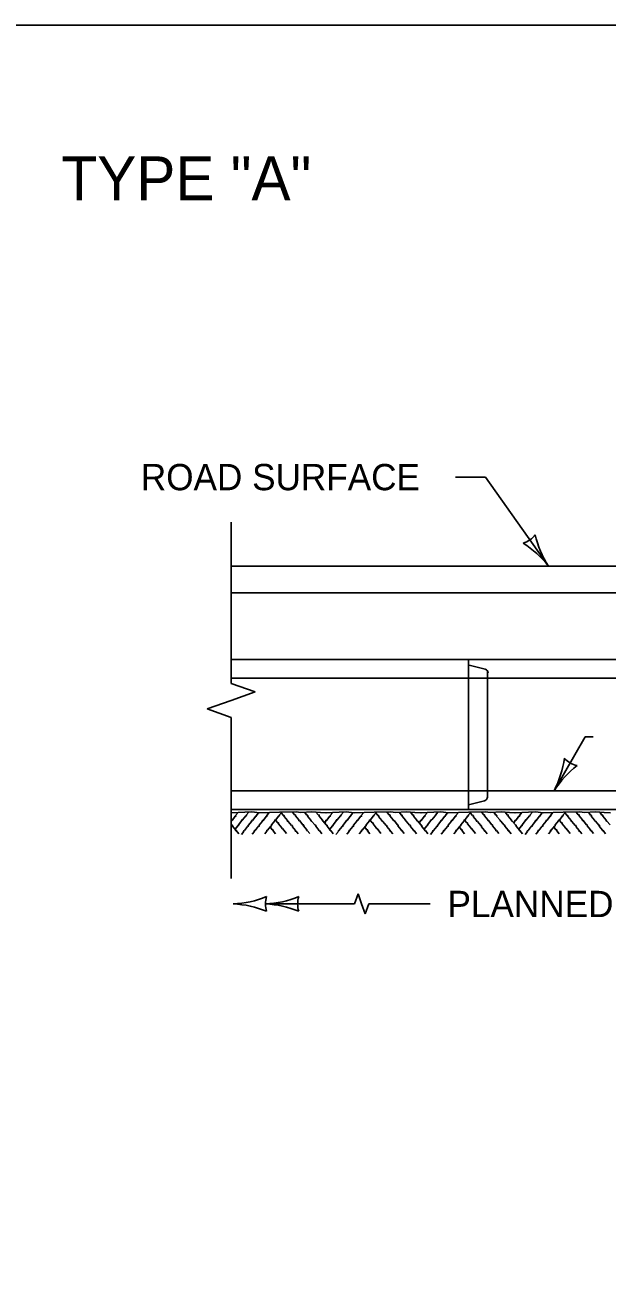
# Model space of a CAD drawing. Extents: x 49991.4 to 50021, y 49987.6 to 50011.4.
# Drawn here: x 50003.231 to 50004.56, y 49996.145 to 49998.999 of the extents above; entities that cross this region are included whole.
import ezdxf

# ---------------------------------------------------------------- set-up
doc = ezdxf.new("R2010")
doc.units = 0
for name, color, linetype in [('Level 1', 7, 'Continuous'), ('Level 2', 7, 'Continuous'), ('Level 3', 7, 'Continuous'), ('Level 4', 7, 'Continuous'), ('Level 6', 7, 'Continuous')]:
    doc.layers.add(name, color=color, linetype=linetype)

msp = doc.modelspace()

# ---------------------------------------------------------------- linework, layer by layer
at = {"layer": 'Level 1'}
for p, q in [((50003.7019, 49997.7029), (50003.702, 49997.7636)), ((50003.702, 49997.7636), (50004.9281, 49997.7636)), ((50005.2161, 49997.7029), (50003.7019, 49997.7029)), ((50003.7036, 49997.7029), (50003.7047, 49997.7029)), ((50003.702, 49997.5504), (50005.9421, 49997.5504)), ((50004.2441, 49997.5504), (50004.2441, 49997.208)), ((50006.3273, 49997.208), (50003.702, 49997.208))]:
    msp.add_line(p, q, dxfattribs=at)
msp.add_lwpolyline([(49999.3835, 49998.9992), (50016.7501, 49998.9992), (50016.7501, 49987.7988), (49999.3835, 49987.7988)], close=True, dxfattribs=at)
for points in [[(50003.7015, 49997.2006), (50003.7485, 49997.2025), (50003.7665, 49997.2004), (50003.8121, 49997.2019), (50003.8505, 49997.2022), (50003.8609, 49997.2007), (50003.8861, 49997.2025), (50003.9055, 49997.2013), (50003.9201, 49997.2006)], [(50003.7179, 49997.2012), (50003.7119, 49997.1941), (50003.7125, 49997.1926), (50003.7109, 49997.1926), (50003.7037, 49997.183), (50003.7029, 49997.183)], [(50003.742, 49997.202), (50003.736, 49997.195), (50003.7367, 49997.1936), (50003.7353, 49997.1936), (50003.7279, 49997.184), (50003.7258, 49997.184), (50003.7263, 49997.1824), (50003.7185, 49997.1726), (50003.7185, 49997.171), (50003.7168, 49997.1704), (50003.7108, 49997.1626)], [(50003.7639, 49997.2004), (50003.7585, 49997.1936), (50003.7589, 49997.1923), (50003.7577, 49997.1923), (50003.7503, 49997.1827), (50003.7483, 49997.1827), (50003.7485, 49997.181), (50003.7408, 49997.1713), (50003.7408, 49997.1696), (50003.7391, 49997.1689), (50003.7319, 49997.1596), (50003.7301, 49997.1593), (50003.7305, 49997.1576), (50003.7253, 49997.151)], [(50003.7888, 49997.2012), (50003.7828, 49997.1941), (50003.7835, 49997.1926), (50003.7821, 49997.1926), (50003.7749, 49997.183), (50003.7727, 49997.183), (50003.7729, 49997.1812), (50003.7654, 49997.1718), (50003.7654, 49997.1698), (50003.7635, 49997.1692), (50003.7564, 49997.1598), (50003.7545, 49997.1598), (50003.7549, 49997.1578), (50003.7497, 49997.1515)], [(50003.8173, 49997.202), (50003.8115, 49997.1947), (50003.8121, 49997.1935), (50003.8109, 49997.1935), (50003.8033, 49997.1839), (50003.8014, 49997.1839), (50003.8015, 49997.1822), (50003.7939, 49997.1726), (50003.7939, 49997.1707), (50003.7923, 49997.1702), (50003.7849, 49997.1608), (50003.7833, 49997.1606), (50003.7835, 49997.1587), (50003.7783, 49997.1524)], [(50003.8547, 49997.1524), (50003.8499, 49997.1587), (50003.8483, 49997.1584), (50003.8487, 49997.1598), (50003.841, 49997.169), (50003.8415, 49997.171), (50003.8397, 49997.1712), (50003.832, 49997.1808), (50003.8303, 49997.1812), (50003.8301, 49997.183), (50003.8225, 49997.1922), (50003.8229, 49997.1941), (50003.8211, 49997.1941), (50003.8158, 49997.2006)], [(50003.8811, 49997.153), (50003.8755, 49997.1602), (50003.874, 49997.1599), (50003.8743, 49997.1612), (50003.8667, 49997.1706), (50003.8673, 49997.1725), (50003.8653, 49997.1726), (50003.8577, 49997.1824), (50003.856, 49997.1827), (50003.8559, 49997.1845), (50003.8483, 49997.1936), (50003.8485, 49997.1956), (50003.8465, 49997.1956), (50003.8415, 49997.202)], [(50003.9089, 49997.1522), (50003.9034, 49997.1596), (50003.9019, 49997.1592), (50003.9021, 49997.1605), (50003.8949, 49997.1701), (50003.8951, 49997.1718), (50003.8933, 49997.172), (50003.8855, 49997.1816), (50003.8839, 49997.1821), (50003.8837, 49997.1838), (50003.8763, 49997.193), (50003.8764, 49997.1947), (50003.8745, 49997.1947), (50003.8695, 49997.2016)], [(50003.919, 49997.1726), (50003.9118, 49997.1816), (50003.9101, 49997.1822), (50003.91, 49997.1839), (50003.9023, 49997.193), (50003.9027, 49997.195), (50003.9009, 49997.195), (50003.8953, 49997.2019)], [(50003.9175, 49997.2006), (50003.9645, 49997.2025), (50003.9823, 49997.2004), (50004.0281, 49997.2019), (50004.0665, 49997.2022), (50004.0773, 49997.2007), (50004.1021, 49997.2025), (50004.1213, 49997.2013), (50004.1361, 49997.2006)], [(50003.9339, 49997.2012), (50003.9279, 49997.1941), (50003.9285, 49997.1926), (50003.9269, 49997.1926), (50003.9197, 49997.183), (50003.9189, 49997.183)], [(50003.958, 49997.202), (50003.952, 49997.195), (50003.9527, 49997.1936), (50003.9513, 49997.1936), (50003.9439, 49997.184), (50003.9418, 49997.184), (50003.9423, 49997.1824), (50003.9345, 49997.1726), (50003.9345, 49997.171), (50003.9328, 49997.1704), (50003.9267, 49997.1626)], [(50003.9799, 49997.2004), (50003.9743, 49997.1936), (50003.9749, 49997.1923), (50003.9735, 49997.1923), (50003.9663, 49997.1827), (50003.9643, 49997.1827), (50003.9645, 49997.181), (50003.9568, 49997.1713), (50003.9568, 49997.1696), (50003.9551, 49997.1689), (50003.9478, 49997.1596), (50003.9461, 49997.1593), (50003.9465, 49997.1576), (50003.9411, 49997.151)], [(50004.0048, 49997.2012), (50003.9987, 49997.1941), (50003.9994, 49997.1926), (50003.9981, 49997.1926), (50003.9905, 49997.183), (50003.9887, 49997.183), (50003.9889, 49997.1812), (50003.9813, 49997.1718), (50003.9813, 49997.1698), (50003.9795, 49997.1692), (50003.9723, 49997.1598), (50003.9705, 49997.1598), (50003.9709, 49997.1578), (50003.9657, 49997.1515)], [(50004.0333, 49997.202), (50004.0273, 49997.1947), (50004.0281, 49997.1935), (50004.0265, 49997.1935), (50004.0193, 49997.1839), (50004.0174, 49997.1839), (50004.0175, 49997.1822), (50004.0099, 49997.1726), (50004.0099, 49997.1707), (50004.0083, 49997.1702), (50004.0009, 49997.1608), (50003.9993, 49997.1606), (50003.9995, 49997.1587), (50003.9941, 49997.1524)], [(50004.0707, 49997.1524), (50004.0659, 49997.1587), (50004.0643, 49997.1584), (50004.0645, 49997.1598), (50004.057, 49997.169), (50004.0573, 49997.171), (50004.0557, 49997.1712), (50004.048, 49997.1808), (50004.0463, 49997.1812), (50004.0461, 49997.183), (50004.0385, 49997.1922), (50004.0389, 49997.1941), (50004.0369, 49997.1941), (50004.0318, 49997.2006)], [(50004.0971, 49997.153), (50004.0915, 49997.1602), (50004.09, 49997.1599), (50004.0901, 49997.1612), (50004.0827, 49997.1706), (50004.0829, 49997.1725), (50004.0813, 49997.1726), (50004.0737, 49997.1824), (50004.072, 49997.1827), (50004.0719, 49997.1845), (50004.0643, 49997.1936), (50004.0645, 49997.1956), (50004.0625, 49997.1956), (50004.0575, 49997.202)], [(50004.1249, 49997.1522), (50004.1194, 49997.1596), (50004.1179, 49997.1592), (50004.1181, 49997.1605), (50004.1105, 49997.1701), (50004.111, 49997.1718), (50004.1093, 49997.172), (50004.1015, 49997.1816), (50004.0999, 49997.1821), (50004.0997, 49997.1838), (50004.0923, 49997.193), (50004.0924, 49997.1947), (50004.0905, 49997.1947), (50004.0855, 49997.2016)], [(50004.135, 49997.1726), (50004.1278, 49997.1816), (50004.126, 49997.1822), (50004.1259, 49997.1839), (50004.1183, 49997.193), (50004.1185, 49997.195), (50004.1165, 49997.195), (50004.1113, 49997.2019)], [(50004.1335, 49997.2006), (50004.1805, 49997.2025), (50004.1983, 49997.2004), (50004.2441, 49997.2019), (50004.2825, 49997.2022), (50004.2929, 49997.2007), (50004.318, 49997.2025), (50004.3373, 49997.2013), (50004.3521, 49997.2006)], [(50004.1499, 49997.2012), (50004.1439, 49997.1941), (50004.1445, 49997.1926), (50004.1429, 49997.1926), (50004.1357, 49997.183), (50004.1349, 49997.183)], [(50004.1739, 49997.202), (50004.168, 49997.195), (50004.1685, 49997.1936), (50004.1673, 49997.1936), (50004.1597, 49997.184), (50004.1578, 49997.184), (50004.1579, 49997.1824), (50004.1503, 49997.1726), (50004.1503, 49997.171), (50004.1487, 49997.1704), (50004.1427, 49997.1626)], [(50004.1959, 49997.2004), (50004.1905, 49997.1936), (50004.1909, 49997.1923), (50004.1897, 49997.1923), (50004.1823, 49997.1827), (50004.1803, 49997.1827), (50004.1805, 49997.181), (50004.1728, 49997.1713), (50004.1728, 49997.1696), (50004.1711, 49997.1689), (50004.1638, 49997.1596), (50004.162, 49997.1593), (50004.1623, 49997.1576), (50004.1571, 49997.151)], [(50004.2208, 49997.2012), (50004.2147, 49997.1941), (50004.2154, 49997.1926), (50004.2141, 49997.1926), (50004.2065, 49997.183), (50004.2047, 49997.183), (50004.2049, 49997.1812), (50004.1973, 49997.1718), (50004.1973, 49997.1698), (50004.1955, 49997.1692), (50004.1883, 49997.1598), (50004.1865, 49997.1598), (50004.1867, 49997.1578), (50004.1815, 49997.1515)], [(50004.2493, 49997.202), (50004.2433, 49997.1947), (50004.2441, 49997.1935), (50004.2425, 49997.1935), (50004.2353, 49997.1839), (50004.2334, 49997.1839), (50004.2335, 49997.1822), (50004.2259, 49997.1726), (50004.2259, 49997.1707), (50004.2243, 49997.1702), (50004.2169, 49997.1608), (50004.2149, 49997.1606), (50004.2154, 49997.1587), (50004.2101, 49997.1524)], [(50004.2867, 49997.1524), (50004.2819, 49997.1587), (50004.2803, 49997.1584), (50004.2805, 49997.1598), (50004.273, 49997.169), (50004.2733, 49997.171), (50004.2717, 49997.1712), (50004.264, 49997.1808), (50004.2623, 49997.1812), (50004.2621, 49997.183), (50004.2544, 49997.1922), (50004.2549, 49997.1941), (50004.2529, 49997.1941), (50004.2478, 49997.2006)], [(50004.3129, 49997.153), (50004.3075, 49997.1602), (50004.306, 49997.1599), (50004.3061, 49997.1612), (50004.2987, 49997.1706), (50004.2989, 49997.1725), (50004.2973, 49997.1726), (50004.2897, 49997.1824), (50004.288, 49997.1827), (50004.2879, 49997.1845), (50004.2801, 49997.1936), (50004.2805, 49997.1956), (50004.2785, 49997.1956), (50004.2735, 49997.202)], [(50004.3408, 49997.1522), (50004.3354, 49997.1596), (50004.3337, 49997.1592), (50004.3341, 49997.1605), (50004.3265, 49997.1701), (50004.327, 49997.1718), (50004.3253, 49997.172), (50004.3175, 49997.1816), (50004.3159, 49997.1821), (50004.3157, 49997.1838), (50004.3079, 49997.193), (50004.3084, 49997.1947), (50004.3065, 49997.1947), (50004.3015, 49997.2016)], [(50004.3509, 49997.1726), (50004.3437, 49997.1816), (50004.342, 49997.1822), (50004.3419, 49997.1839), (50004.3343, 49997.193), (50004.3345, 49997.195), (50004.3325, 49997.195), (50004.3273, 49997.2019)], [(50004.3495, 49997.2006), (50004.3965, 49997.2025), (50004.4143, 49997.2004), (50004.4599, 49997.2019), (50004.4983, 49997.2022), (50004.5089, 49997.2007), (50004.534, 49997.2025), (50004.5533, 49997.2013), (50004.5679, 49997.2006)], [(50004.3659, 49997.2012), (50004.3599, 49997.1941), (50004.3605, 49997.1926), (50004.3589, 49997.1926), (50004.3515, 49997.183), (50004.3505, 49997.183)], [(50004.3899, 49997.202), (50004.3839, 49997.195), (50004.3845, 49997.1936), (50004.3833, 49997.1936), (50004.3757, 49997.184), (50004.3738, 49997.184), (50004.3739, 49997.1824), (50004.3663, 49997.1726), (50004.3663, 49997.171), (50004.3647, 49997.1704), (50004.3587, 49997.1626)], [(50004.4119, 49997.2004), (50004.4063, 49997.1936), (50004.4069, 49997.1923), (50004.4055, 49997.1923), (50004.3983, 49997.1827), (50004.3963, 49997.1827), (50004.3965, 49997.181), (50004.3888, 49997.1713), (50004.3888, 49997.1696), (50004.3871, 49997.1689), (50004.3798, 49997.1596), (50004.378, 49997.1593), (50004.3783, 49997.1576), (50004.3731, 49997.151)], [(50004.4367, 49997.2012), (50004.4307, 49997.1941), (50004.4314, 49997.1926), (50004.4299, 49997.1926), (50004.4225, 49997.183), (50004.4207, 49997.183), (50004.4209, 49997.1812), (50004.4133, 49997.1718), (50004.4133, 49997.1698), (50004.4115, 49997.1692), (50004.4043, 49997.1598), (50004.4023, 49997.1598), (50004.4027, 49997.1578), (50004.3975, 49997.1515)], [(50004.4651, 49997.202), (50004.4593, 49997.1947), (50004.4601, 49997.1935), (50004.4585, 49997.1935), (50004.4513, 49997.1839), (50004.4493, 49997.1839), (50004.4495, 49997.1822), (50004.4419, 49997.1726), (50004.4419, 49997.1707), (50004.4403, 49997.1702), (50004.4329, 49997.1608), (50004.4309, 49997.1606), (50004.4314, 49997.1587), (50004.4261, 49997.1524)], [(50004.5027, 49997.1524), (50004.4979, 49997.1587), (50004.4961, 49997.1584), (50004.4965, 49997.1598), (50004.489, 49997.169), (50004.4893, 49997.171), (50004.4877, 49997.1712), (50004.48, 49997.1808), (50004.4783, 49997.1812), (50004.4781, 49997.183), (50004.4704, 49997.1922), (50004.4709, 49997.1941), (50004.4689, 49997.1941), (50004.4638, 49997.2006)], [(50004.5291, 49997.153), (50004.5235, 49997.1602), (50004.5219, 49997.1599), (50004.5221, 49997.1612), (50004.5147, 49997.1706), (50004.5149, 49997.1725), (50004.5133, 49997.1726), (50004.5057, 49997.1824), (50004.504, 49997.1827), (50004.5039, 49997.1845), (50004.4961, 49997.1936), (50004.4965, 49997.1956), (50004.4945, 49997.1956), (50004.4895, 49997.202)], [(50004.5568, 49997.1522), (50004.5514, 49997.1596), (50004.5497, 49997.1592), (50004.5501, 49997.1605), (50004.5425, 49997.1701), (50004.543, 49997.1718), (50004.5411, 49997.172), (50004.5335, 49997.1816), (50004.5319, 49997.1821), (50004.5315, 49997.1838), (50004.5239, 49997.193), (50004.5244, 49997.1947), (50004.5225, 49997.1947), (50004.5175, 49997.2016)], [(50004.5669, 49997.1726), (50004.5597, 49997.1816), (50004.558, 49997.1822), (50004.5579, 49997.1839), (50004.5503, 49997.193), (50004.5505, 49997.195), (50004.5485, 49997.195), (50004.5433, 49997.2019)], [(50003.7189, 49997.1524), (50003.7133, 49997.1598), (50003.7119, 49997.1593), (50003.7121, 49997.1606), (50003.7047, 49997.1701), (50003.7049, 49997.1719), (50003.7031, 49997.172), (50003.7029, 49997.1726)], [(50003.8027, 49997.1527), (50003.7973, 49997.1593), (50003.7975, 49997.1612), (50003.7955, 49997.1612), (50003.7905, 49997.168)], [(50003.8277, 49997.1532), (50003.8189, 49997.1642), (50003.8173, 49997.1646), (50003.8171, 49997.1662), (50003.8097, 49997.1755), (50003.8098, 49997.1773), (50003.808, 49997.1773), (50003.8031, 49997.1839)], [(50003.9189, 49997.183), (50003.9178, 49997.183), (50003.9179, 49997.1812), (50003.9153, 49997.1778)], [(50003.9347, 49997.1524), (50003.9293, 49997.1598), (50003.9279, 49997.1593), (50003.928, 49997.1606), (50003.9207, 49997.1701), (50003.9209, 49997.1719), (50003.9191, 49997.172), (50003.9185, 49997.1726)], [(50004.0185, 49997.1527), (50004.0133, 49997.1593), (50004.0135, 49997.1612), (50004.0115, 49997.1612), (50004.0065, 49997.168)], [(50004.0437, 49997.1532), (50004.0349, 49997.1642), (50004.0333, 49997.1646), (50004.0331, 49997.1662), (50004.0257, 49997.1755), (50004.0258, 49997.1773), (50004.024, 49997.1773), (50004.0191, 49997.1839)], [(50004.1349, 49997.183), (50004.1338, 49997.183), (50004.1339, 49997.1812), (50004.1313, 49997.1778)], [(50004.1507, 49997.1524), (50004.1453, 49997.1598), (50004.1439, 49997.1593), (50004.1441, 49997.1606), (50004.1365, 49997.1701), (50004.1369, 49997.1719), (50004.1351, 49997.172), (50004.1349, 49997.1726)], [(50004.2345, 49997.1527), (50004.2293, 49997.1593), (50004.2295, 49997.1612), (50004.2275, 49997.1612), (50004.2225, 49997.168)], [(50004.2597, 49997.1532), (50004.2509, 49997.1642), (50004.2493, 49997.1646), (50004.2491, 49997.1662), (50004.2417, 49997.1755), (50004.2418, 49997.1773), (50004.24, 49997.1773), (50004.2349, 49997.1839)], [(50004.3509, 49997.183), (50004.3498, 49997.183), (50004.3499, 49997.1812), (50004.3473, 49997.1778)], [(50004.3667, 49997.1524), (50004.3613, 49997.1598), (50004.3599, 49997.1593), (50004.36, 49997.1606), (50004.3525, 49997.1701), (50004.3528, 49997.1719), (50004.3511, 49997.172), (50004.3505, 49997.1726)], [(50004.4505, 49997.1527), (50004.4451, 49997.1593), (50004.4455, 49997.1612), (50004.4435, 49997.1612), (50004.4383, 49997.168)], [(50004.4757, 49997.1532), (50004.4669, 49997.1642), (50004.4653, 49997.1646), (50004.4651, 49997.1662), (50004.4575, 49997.1755), (50004.4578, 49997.1773), (50004.456, 49997.1773), (50004.4509, 49997.1839)]]:
    msp.add_lwpolyline(points, dxfattribs=at)
at = {"layer": 'Level 2'}
msp.add_line((50016.7501, 49998.9992), (49999.3835, 49998.9992), dxfattribs=at)
at = {"layer": 'Level 3'}
for p, q in [((50004.2137, 49997.9669), (50004.2822, 49997.9669)), ((50004.2822, 49997.9669), (50004.4264, 49997.7636)), ((50004.5103, 49997.3741), (50004.4392, 49997.2508)), ((50004.5103, 49997.3741), (50004.5282, 49997.3741)), ((50003.9834, 49996.9922), (50003.78, 49996.9922)), ((50003.9915, 49997.015), (50003.9834, 49996.9922)), ((50003.9915, 49997.015), (50003.9996, 49996.9922)), ((50003.9996, 49996.9922), (50004.0077, 49996.9694)), ((50004.0158, 49996.9922), (50004.0077, 49996.9694)), ((50004.1558, 49996.9922), (50004.0158, 49996.9922))]:
    msp.add_line(p, q, dxfattribs=at)
for centre, radius, start, end in [((50004.3522, 49997.8682), 0.0548, 287.4837, 323.2061), ((50004.6129, 49997.8846), 0.2223, 192.8009, 212.9844), ((50004.2432, 49997.6196), 0.233, 38.1722, 57.422), ((50004.2319, 49997.3571), 0.233, 332.8577, 352.1076), ((50004.6271, 49997.1319), 0.2223, 127.4864, 147.67), ((50004.5032, 49997.3619), 0.0548, 222.1693, 257.8916), ((50003.6951, 49997.2249), 0.233, 272.8273, 292.0772), ((50003.6974, 49996.7701), 0.2223, 67.456, 87.6395), ((50003.8348, 49996.9922), 0.0548, 162.1388, 197.8612), ((50003.7685, 49997.2249), 0.233, 272.8273, 292.0772), ((50003.7709, 49996.7701), 0.2223, 67.456, 87.6395), ((50003.9083, 49996.9922), 0.0548, 162.1388, 197.8612)]:
    msp.add_arc(centre, radius, start, end, dxfattribs=at)
at = {"layer": 'Level 4'}
for p, q in [((50004.2456, 49997.5373), (50004.282, 49997.5281)), ((50003.702, 49997.5077), (50005.9483, 49997.5077)), ((50004.287, 49997.5221), (50004.287, 49997.2363)), ((50003.702, 49997.2508), (50006.3273, 49997.2508)), ((50004.2441, 49997.2188), (50004.2805, 49997.2279))]:
    msp.add_line(p, q, dxfattribs=at)
for centre, start, end in [((50004.2799, 49997.5198), 0, 75.8703), ((50004.2784, 49997.2362), 284.1107, 0)]:
    msp.add_arc(centre, 0.00856, start, end, dxfattribs=at)
at = {"layer": 'Level 6'}
for p, q in [((50003.702, 49997.8636), (50003.702, 49997.4959)), ((50003.7568, 49997.4764), (50003.702, 49997.4959)), ((50003.7568, 49997.4764), (50003.702, 49997.457)), ((50003.702, 49997.457), (50003.6472, 49997.4376)), ((50003.702, 49997.4181), (50003.6472, 49997.4376)), ((50003.702, 49997.4181), (50003.702, 49997.0505))]:
    msp.add_line(p, q, dxfattribs=at)

# ---------------------------------------------------------------- texts
at = {"layer": 'Level 2'}
for s, height, p in [('TYPE "A"', 0.1, (50003.3142, 49998.5992)), ('ROAD SURFACE', 0.06, (50003.4954, 49997.9369)), ('PLANNED CULVERT LENGTH', 0.06, (50004.1958, 49996.9622))]:
    msp.add_text(s, height=height, dxfattribs=at).set_placement(p)

doc.saveas('drawing.dxf')
